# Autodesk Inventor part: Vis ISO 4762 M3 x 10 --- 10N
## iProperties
Created: 2011-01
Part Number: Vis ISO 4762 M3 x 10 --- 10N
Document SubType Name: Modeling
Designer: eric
Density: 1 g/cm^3
Mass: 0.132905 g
Surface Area: 2.02752 cm^2
Volume: 0.132905 cm^3
Author: eric
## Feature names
1. Base1
